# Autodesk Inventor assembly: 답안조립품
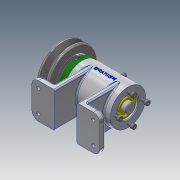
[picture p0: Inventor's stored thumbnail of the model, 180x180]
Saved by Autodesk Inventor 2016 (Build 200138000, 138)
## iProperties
Created: 2017-02
Part Number: 답안조립품
Material: 일반
Document SubType Name: Assembly
Designer: CAMTIC
Author: CAMTIC
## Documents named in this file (16)
- C:\Users\CAMTIC\Desktop\470207V1033\답안조립품.iam
- C:\Users\CAMTIC\Desktop\470207V1033\본체.ipt
- C:\Users\CAMTIC\Desktop\470207V1033\V벨트풀리.ipt
- C:\Users\CAMTIC\Desktop\470207V1033\너트 M 8.ipt
- C:\Users\CAMTIC\Desktop\470207V1033\니플 M 6 x 0.75.ipt
- C:\Users\CAMTIC\Desktop\470207V1033\뒤커버.ipt
- C:\Users\CAMTIC\Desktop\470207V1033\베어링 15 x 32 x 9.ipt
- C:\Users\CAMTIC\Desktop\470207V1033\볼트 M 6 x 8.ipt
- C:\Users\CAMTIC\Desktop\470207V1033\볼트 M4 x 12.ipt
- C:\Users\CAMTIC\Desktop\470207V1033\스프링와셔 8.ipt
- C:\Users\CAMTIC\Desktop\470207V1033\앞커버.ipt
- C:\Users\CAMTIC\Desktop\470207V1033\오일 실 15 25 7.ipt
- C:\Users\CAMTIC\Desktop\470207V1033\와셔 6x11.5.ipt
- C:\Users\CAMTIC\Desktop\470207V1033\와셔 8x17.ipt
- C:\Users\CAMTIC\Desktop\470207V1033\축.ipt
- C:\Users\CAMTIC\Desktop\470207V1033\키 3 x 3 x 12.ipt
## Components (11 placed, 3 different names)
1. V벨트풀리:1
2. KS B 2023 6002 - 15 x 32 x 9:1
3. KS B 2023 6002 - 15 x 32 x 9:2
4. ISO 4762 M4 x 12:1
5. ISO 4762 M4 x 12:3
6. ISO 4762 M4 x 12:4
7. ISO 4762 M4 x 12:5
8. ISO 4762 M4 x 12:2
9. ISO 4762 M4 x 12:6
10. ISO 4762 M4 x 12:7
11. ISO 4762 M4 x 12:8
